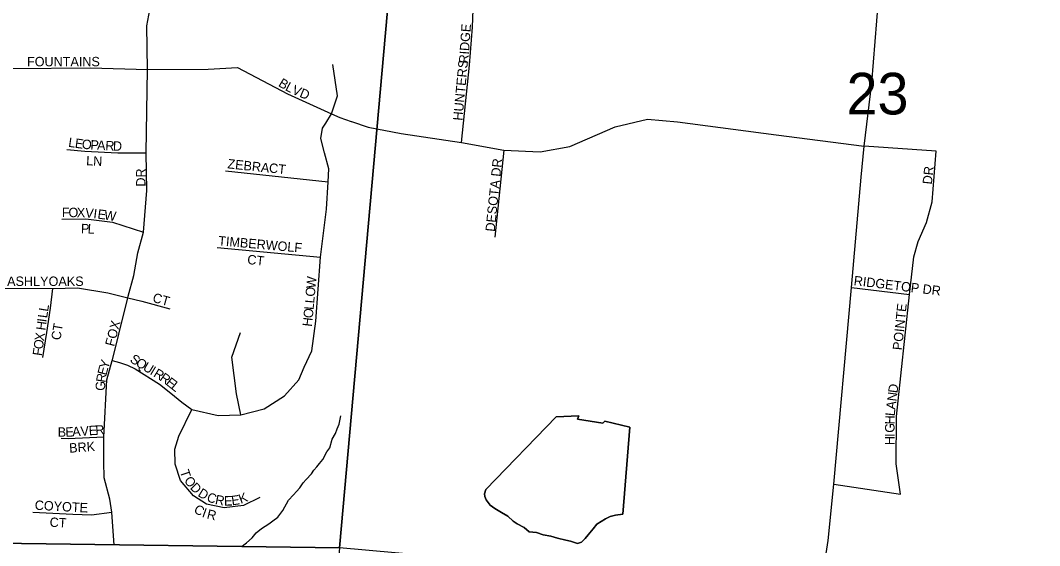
# Model space of a CAD drawing. Extents: x 1310247 to 1552180, y 377264 to 706493.
# Drawn here: x 1428065 to 1433472, y 494835 to 497623 of the extents above; entities that cross this region are included whole.
import ezdxf

# ---------------------------------------------------------------- set-up
doc = ezdxf.new("R2010")
doc.units = 0
for name, color, linetype in [('GM_X_County_Road', 7, 'Continuous'), ('GM_X_Minor_Lake', 7, 'Continuous'), ('GM_X_Minor_River', 7, 'Continuous'), ('GM_X_Section', 7, 'Continuous'), ('GM_X_Section_Text', 7, 'Continuous'), ('GM_X_Township_Subdivision', 7, 'Continuous'), ('GM_X_Township_Subdivision_Text', 7, 'Continuous')]:
    doc.layers.add(name, color=color, linetype=linetype)

msp = doc.modelspace()

# ---------------------------------------------------------------- linework, layer by layer
at = {"layer": 'GM_X_County_Road'}
msp.add_lwpolyline([(1431381.6, 492987.5), (1431385.2, 492992.3), (1431497.9, 493159), (1431713.4, 493434.6), (1431820.6, 493596.1), (1432120.9, 494091.1), (1432177.2, 494235.8), (1432285.4, 494474.8), (1432325.4, 494638.3), (1432336.7, 494770.6), (1432349.4, 494862.8), (1432380, 495160.6), (1432473.4, 496205.1), (1432525.8, 496791), (1432540.5, 496955.1), (1432582.1, 497292.2), (1432617.5, 497731.2), (1432712.9, 500020.8)], dxfattribs=at)
at = {"layer": 'GM_X_Minor_Lake'}
for points in [[(1430906.5, 495519), (1430533.7, 495133.1), (1430527.1, 495109.2), (1430528.8, 495095.1), (1430536.4, 495078.8), (1430557.7, 495050.2), (1430581.3, 495031.5), (1430616.9, 495010.5), (1430650.5, 494991.6), (1430679.9, 494964.8), (1430699.6, 494950.2), (1430737.2, 494931.2), (1430764.7, 494908.4), (1430802.8, 494905.4), (1430838.6, 494892.5), (1430878.5, 494885.4), (1430914.3, 494874.5), (1430958.1, 494863.3), (1430984.1, 494858.7), (1431019.9, 494845.7), (1431042.1, 494853.2), (1431060.7, 494872.8), (1431077.2, 494892.4), (1431104.1, 494923.8), (1431122.8, 494949.5), (1431169.6, 494976.4), (1431194, 494989.8), (1431222.2, 494997.1), (1431260.5, 495002.2), (1431298.1, 495462.9)], [(1431298.1, 495462.9), (1431164.6, 495496.4), (1431154.3, 495484.6), (1431020.4, 495506.1), (1431026.9, 495524), (1430906.5, 495519)]]:
    msp.add_lwpolyline(points, dxfattribs=at)
at = {"layer": 'GM_X_Minor_River'}
for points in [[(1429564.5, 495168.2), (1429580.8, 495185.9), (1429609.3, 495215.4), (1429621.7, 495235.3), (1429638.1, 495253), (1429652.4, 495270.8), (1429668.8, 495292.5), (1429691.6, 495332.2), (1429706, 495354), (1429718.9, 495399.9), (1429737.5, 495429.7), (1429746, 495455.6), (1429756.5, 495479.5), (1429765.3, 495523.5)], [(1431298.1, 495462.9), (1431260.5, 495002.2), (1431222.2, 494997.1), (1431194, 494989.8), (1431169.6, 494976.4), (1431122.8, 494949.5), (1431104.1, 494923.8), (1431077.2, 494892.4), (1431060.7, 494872.8), (1431042.1, 494853.2), (1431019.9, 494845.7), (1430984.1, 494858.7), (1430958.1, 494863.3), (1430914.3, 494874.5), (1430878.5, 494885.4), (1430838.6, 494892.5), (1430802.8, 494905.4), (1430764.7, 494908.4), (1430737.2, 494931.2), (1430699.6, 494950.2), (1430679.9, 494964.8), (1430650.5, 494991.6), (1430616.9, 495010.5), (1430581.3, 495031.5), (1430557.7, 495050.2), (1430536.4, 495078.8), (1430528.8, 495095.1), (1430527.1, 495109.2), (1430533.7, 495133.1), (1430906.5, 495519)], [(1430906.5, 495519), (1431026.9, 495524), (1431020.4, 495506.1), (1431154.3, 495484.6), (1431164.6, 495496.4), (1431298.1, 495462.9)], [(1429244.2, 494833.5), (1429264.5, 494849.1), (1429295, 494876.6), (1429315.5, 494902.2), (1429343.9, 494925.8), (1429382.4, 494951.1), (1429404.6, 494966.7), (1429431, 494986.2), (1429457.7, 495021.8), (1429486.7, 495075.4), (1429513.3, 495105), (1429529.6, 495122.7), (1429548, 495142.4), (1429564.5, 495168.2)]]:
    msp.add_lwpolyline(points, dxfattribs=at)
at = {"layer": 'GM_X_Section'}
for points in [[(1430245.7, 500293), (1429758, 494823.6), (1424307.8, 494896.9), (1424746.1, 500303.3)], [(1430245.7, 500293), (1435471.2, 499726.6), (1434995.6, 494353), (1429758, 494823.6)], [(1429758, 494823.6), (1429255.8, 489324.6), (1423863.5, 489580.6), (1424307.8, 494896.9)]]:
    msp.add_lwpolyline(points, close=True, dxfattribs=at)
at = {"layer": 'GM_X_Township_Subdivision'}
for points in [[(1430405, 496974.2), (1430447, 497385), (1430462.6, 497588.1), (1430467.8, 497681.8), (1430381, 497862.4), (1430257.8, 498112.3), (1430263, 498209.5), (1430283.9, 498497.7), (1430320.3, 498848.3), (1430342.8, 499160.7), (1430387.8, 499286.3), (1430431.5, 499360.4), (1430464.7, 499456.7), (1430486.9, 499542.6), (1430509.4, 499777), (1430561.2, 500234.2)], [(1428562.4, 494836.8), (1428550.2, 495012.2), (1428539.8, 495081.6), (1428510.3, 495194.4), (1428506.9, 495279.5), (1428508.6, 495411.4), (1428524.2, 495715.2), (1428552.8, 495817.7), (1428553.7, 495821), (1428586.7, 495958.2), (1428634.7, 496150.4), (1428637, 496159.5), (1428666.5, 496268.9), (1428687.3, 496388.6), (1428718.6, 496499.8), (1428735.9, 496720.2), (1428733, 496920.3), (1428739.4, 497362.4), (1428735.9, 497594.1), (1428751.5, 497679.2), (1428765.4, 497750.4)], [(1426905.1, 496875.5), (1426997.1, 497014.4), (1427108.1, 497125.5), (1427262.6, 497280), (1427333.7, 497316.4), (1427429.2, 497363.3), (1427522.9, 497391.1), (1427746.8, 497406.7), (1428022.1, 497367.9), (1428437.4, 497371.1), (1428739.4, 497362.4), (1429060.4, 497364.2), (1429216.6, 497373.1), (1429482.9, 497234.2), (1429715.2, 497128), (1429760, 497107.5), (1429820.4, 497086.9)], [(1428552.8, 495817.7), (1428590.5, 495806.7), (1428633.8, 495793), (1428673.2, 495773.7), (1428803.8, 495692.6), (1428863.1, 495644.7), (1428922.3, 495595.8), (1428973.7, 495557.2), (1429114.2, 495525.9), (1429234, 495529.4), (1429358.9, 495560.7), (1429466.5, 495630.1), (1429542.9, 495715.2), (1429570.6, 495782.8), (1429610.5, 495869.6), (1429633.1, 496025.8), (1429657.4, 496366.1), (1429688.6, 496621.3), (1429697.3, 496767.1), (1429700.8, 496834.7), (1429678.2, 496919.8), (1429659.1, 496996.2), (1429667.8, 497051.7), (1429685.2, 497077.7), (1429715.2, 497128), (1429747.6, 497223.6), (1429723.4, 497388.4)], [(1429820.4, 497086.9), (1429821.8, 497086.4), (1429909.3, 497056.6), (1430085.1, 497023.5), (1430405, 496974.2), (1430630.5, 496935.1), (1430822.6, 496926.1), (1430979.1, 496954.4), (1431220.6, 497058), (1431391.3, 497099.6), (1431551.1, 497084.3), (1432075, 497015.2), (1432540.5, 496955.1)], [(1428312.1, 496937.8), (1428406.3, 496928.2), (1428581.2, 496919.5), (1428733, 496920.3)], [(1432380, 495160.6), (1432733.9, 495107.3), (1432711.7, 495269.2), (1432712.8, 495520.1), (1432782.4, 496167.4), (1432804.8, 496368.9), (1432827.1, 496449.3), (1432871.5, 496550.9), (1432901.2, 496659.9), (1432923.4, 496928.7), (1432540.5, 496955.1)], [(1430630.5, 496935.1), (1430581.6, 496472)], [(1429153.8, 496824.1), (1429697.3, 496767.1)], [(1428284.4, 496568.9), (1428412.3, 496570.3), (1428553.7, 496551.8), (1428718.6, 496499.8)], [(1429109.5, 496417.4), (1429657.4, 496366.1)], [(1427878.5, 496201.5), (1428237.9, 496199.4), (1428368, 496202.9), (1428528.4, 496176.6), (1428634.7, 496150.4), (1428708.9, 496132.1), (1428857.4, 496091.8)], [(1428184.4, 495833.1), (1428204.7, 495967.2), (1428225.1, 496095.7), (1428237.9, 496199.4)], [(1432473.4, 496205.1), (1432782.4, 496167.4)], [(1429234, 495529.4), (1429211.2, 495640.1), (1429187, 495836.1), (1429233.4, 495965.9)], [(1429335.4, 495090.7), (1429248, 495048.7), (1429145.4, 495035.6), (1429053, 495055), (1428984.2, 495098.4), (1428913.8, 495180.5), (1428886.4, 495267.2), (1428884.2, 495347.6), (1428906.5, 495416.6), (1428973.7, 495557.2)], [(1428508.6, 495411.4), (1428319.4, 495402.7), (1428281.6, 495402.9)], [(1428130.3, 495012.2), (1428343.7, 495001.7), (1428442.1, 494997.8), (1428550.2, 495012.2)]]:
    msp.add_lwpolyline(points, dxfattribs=at)

# ---------------------------------------------------------------- texts
at = {"layer": 'GM_X_Section_Text'}
msp.add_text('23', height=221, rotation=0, dxfattribs=at).set_placement((1432447.5, 497124))
at = {"layer": 'GM_X_Township_Subdivision_Text'}
for s, rotation, p in [('RIDGE', 85.914, (1430440.5, 497392.8)), ('FOUNTAINS', 0, (1428100.3, 497379.5)), ('HUNTERS', 84.6438, (1430409.7, 497089.4)), ('B', 328.624, (1429429.7, 497276.9)), ('L', 331.8732, (1429466.2, 497254.8)), ('V', 336.9432, (1429501.5, 497236.1)), ('D', 337.3786, (1429542.3, 497218.7)), ('L', 351.9549, (1428317.3, 496952.6)), ('E', 351.9564, (1428352.1, 496947.7)), ('O', 354.626, (1428389.5, 496942.5)), ('P', 357.0251, (1428435.6, 496938.2)), ('A', 357.1499, (1428470.9, 496936.4)), ('R', 357.1535, (1428514.8, 496934.2)), ('D', 358.1744, (1428555.3, 496932.2)), ('LN', 356.983, (1428413.1, 496854.5)), ('ZEBRA', 353.7978, (1429161.7, 496838.3)), ('DESOTA DR', 84.1443, (1430581.4, 496499.9)), ('DR', 90, (1428728.9, 496740.9)), ('CT', 353.6571, (1429381.8, 496816.3)), ('DR', 83.994, (1432900.2, 496750.7)), ('F', 359.918, (1428285.1, 496578.7)), ('O', 359.9126, (1428320.3, 496578.7)), ('X', 359.2677, (1428364.2, 496578.6)), ('V', 354.6483, (1428407.1, 496578.1)), ('I', 352.8126, (1428450.5, 496574)), ('E', 352.6446, (1428472.3, 496571.3)), ('W', 351.6737, (1428506.9, 496566.8)), ('P', 358.2511, (1428385.9, 496493.6)), ('L', 355.9261, (1428420.6, 496492.6)), ('TIMBERWOLF', 355.0307, (1429113.1, 496429.1)), ('CT', 353.6631, (1429266.7, 496330.4)), ('ASHLY', 0, (1427994.7, 496213.5)), ('OAKS', 0, (1428214.7, 496213.5)), ('W', 84.8063, (1429630.5, 496198.7)), ('RIDGETOP DR', 353.1066, (1432483.8, 496217.9)), ('O', 84.8117, (1429626.5, 496154.9)), ('CT', 344.4724, (1428762.8, 496129.6)), ('L', 84.8089, (1429623.3, 496119.8)), ('L', 82.0915, (1428206.8, 496040.6)), ('L', 80.8498, (1428211.6, 496075.2)), ('O', 84.6147, (1429616, 496040.8)), ('L', 84.8089, (1429620.1, 496084.8)), ('POINTE', 84.1724, (1432741.8, 495870.7)), ('H', 82.0955, (1428197.8, 495975.3)), ('I', 82.0832, (1428203.8, 496018.9)), ('CT', 80.5367, (1428277.1, 495923.1)), ('FOX', 75.463, (1428562, 495889.5)), ('H', 82.9888, (1429610.4, 495995.5)), ('X', 82.0951, (1428189.9, 495918.6)), ('O', 82.0951, (1428183.8, 495875)), ('F', 82.0921, (1428179, 495840.2)), ('Y', 72.3509, (1428530, 495769.5)), ('S', 326.632, (1428642.2, 495813.3)), ('Q', 328.1585, (1428672.8, 495793.2)), ('U', 328.9076, (1428710.8, 495769.6)), ('R', 81.1754, (1428515.4, 495698.3)), ('E', 75.2924, (1428521.2, 495736.1)), ('I', 328.8751, (1428748.4, 495746.9)), ('R', 328.3678, (1428767.2, 495735.6)), ('R', 325.0975, (1428800.3, 495715.2)), ('G', 87.0585, (1428513.3, 495655.7)), ('E', 322.0591, (1428832.2, 495693)), ('L', 321.7093, (1428859.9, 495671.4)), ('N', 82.7015, (1432711.9, 495599.1)), ('D', 82.6906, (1432717.5, 495642.7)), ('A', 82.7787, (1432706.4, 495555.5)), ('L', 84.322, (1432702.9, 495520.8)), ('G', 89.9344, (1432702.2, 495434.1)), ('H', 89.0054, (1432702.2, 495477.9)), ('B', 0.1457, (1428263.2, 495412.7)), ('E', 2.1087, (1428304.6, 495412.9)), ('A', 3.8344, (1428341.5, 495414.2)), ('V', 3.8966, (1428385.4, 495417.2)), ('E', 3.8958, (1428429.3, 495420.2)), ('R', 3.9005, (1428464.4, 495422.6)), ('I', 89.9344, (1432702.2, 495412.1)), ('BRK', 3.9429, (1428325.5, 495327.8)), ('H', 89.9344, (1432702.1, 495368.1)), ('T', 288.2881, (1428910.4, 495229.1)), ('O', 308.3941, (1428930.5, 495178.9)), ('D', 314.5213, (1428961.7, 495140.1)), ('D', 328.257, (1429002.7, 495100.5)), ('C', 339.3021, (1429049.6, 495072.8)), ('R', 348.7228, (1429095.3, 495056.3)), ('E', 8.2132, (1429187.8, 495048.4)), ('K', 20.9333, (1429234.3, 495056.4)), ('COYOTE', 356.9352, (1428140.4, 495025.5)), ('C', 327.9637, (1428980.5, 495014.9)), ('E', 0.5101, (1429145.2, 495047.5)), ('I', 340.9681, (1429025.2, 494988.6)), ('R', 346.6049, (1429051.2, 494979.9)), ('CT', 356.8219, (1428219.3, 494935.2))]:
    msp.add_text(s, height=50, rotation=rotation, dxfattribs=at).set_placement(p)

doc.saveas('drawing.dxf')
